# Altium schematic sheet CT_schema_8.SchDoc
size 277 x 170 mm
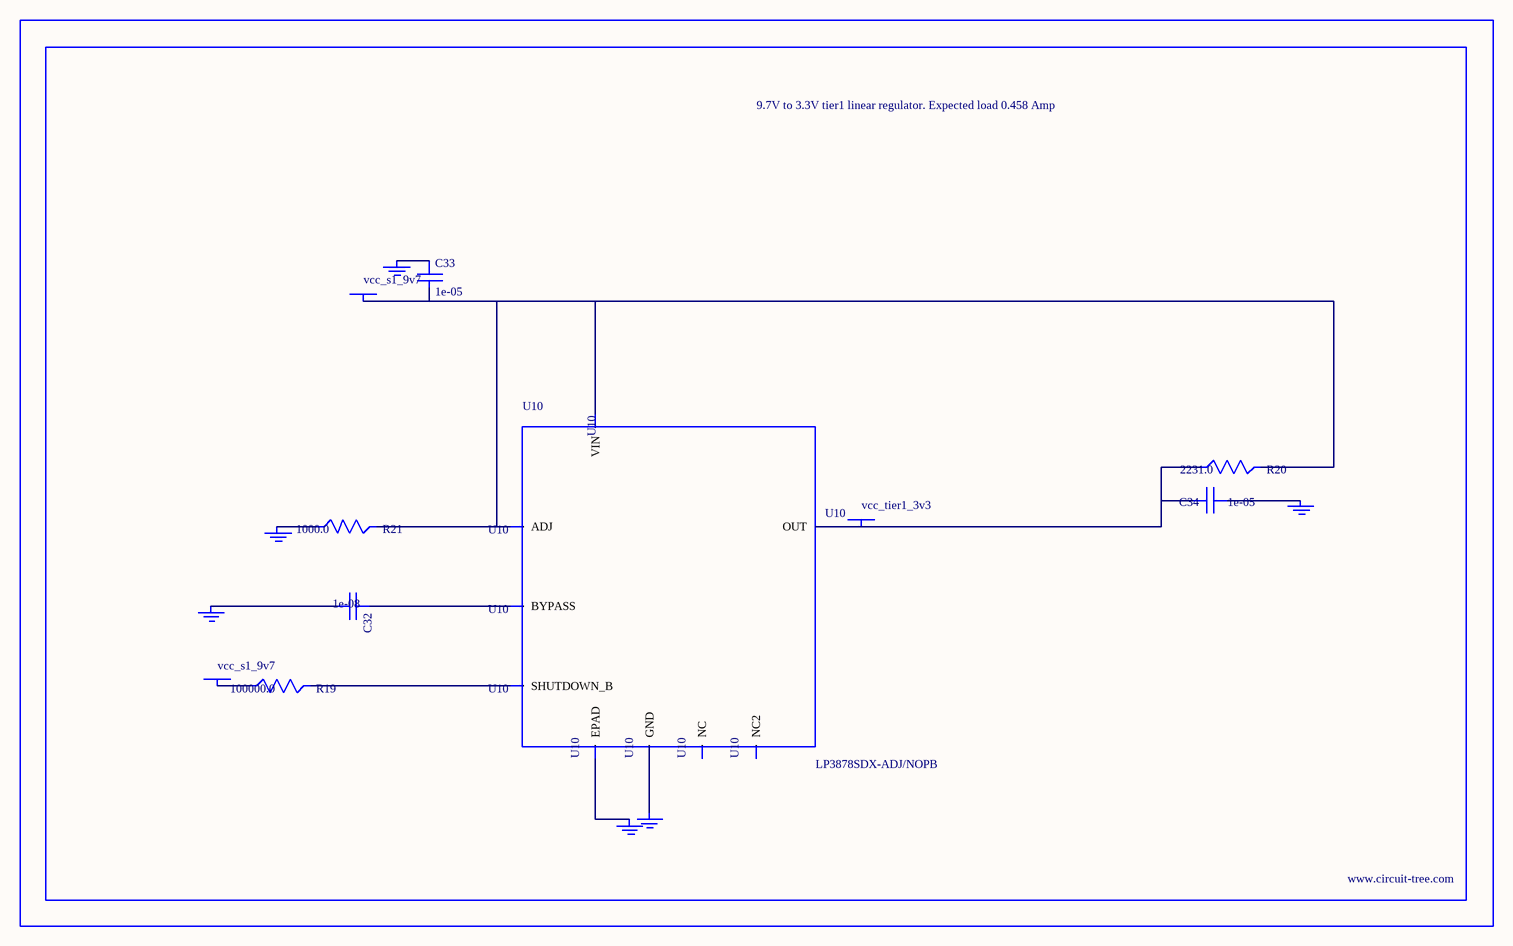
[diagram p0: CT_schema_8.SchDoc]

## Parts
BORDER7  (no value)
C32  1e-08  [C0402]
C33  1e-05  [C1206]
C34  1e-05  [C1210]
GND_INSTANCE_7_0  (no value)
GND_INSTANCE_7_1  (no value)
GND_INSTANCE_7_2  (no value)
GND_INSTANCE_7_3  (no value)
GND_INSTANCE_7_4  (no value)
GND_INSTANCE_7_5  (no value)
POWER_INSTANCE_7_0  vcc_s1_9v7
POWER_INSTANCE_7_1  vcc_s1_9v7
POWER_INSTANCE_7_2  vcc_tier1_3v3
R19  100000.0  [R0603]
R20  2231.0  [R0603]
R21  1000.0  [R0603]
U10  LP3878SDX-ADJ/NOPB  [WSON-8]

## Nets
NetC32_1: C32.1 U10.1(BYPASS)
NetC32_2: C32.2 GND_INSTANCE_7_0.0(GND)
NetC33_1: C33.1 GND_INSTANCE_7_1.0(GND)
NetC33_2: C33.2 POWER_INSTANCE_7_0.0(PWR) R20.2 R21.2 U10.4(VIN) U10.6(ADJ)
NetC34_1: C34.1 GND_INSTANCE_7_2.0(GND)
NetC34_2: C34.2 POWER_INSTANCE_7_2.0(PWR) R20.1 U10.5(OUT)
NetGND_INSTANCE_7_3_0: GND_INSTANCE_7_3.0(GND) R21.1
NetGND_INSTANCE_7_4_0: GND_INSTANCE_7_4.0(GND) U10.PAD(EPAD)
NetGND_INSTANCE_7_5_0: GND_INSTANCE_7_5.0(GND) U10.3(GND)
NetPOWER_INSTANCE_7_1_0: POWER_INSTANCE_7_1.0(PWR) R19.1
NetR19_2: R19.2 U10.8(SHUTDOWN_B)

Not connected (* = marked no-connect by the designer): U10 2(NC) 7(NC2)

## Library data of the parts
BORDER7 = BORDER_PAGE7
C32 = C0402C103K3RAC
C33 = C1206C106K3RACTU
C34 = GRM32DR61E106MA12L
GND_INSTANCE_7_0-GND_INSTANCE_7_5 = GND
POWER_INSTANCE_7_0-POWER_INSTANCE_7_2 = PWR
R19 = RC0603JR-07100KL
R20 = R20
R21 = RC0603JR-071KL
